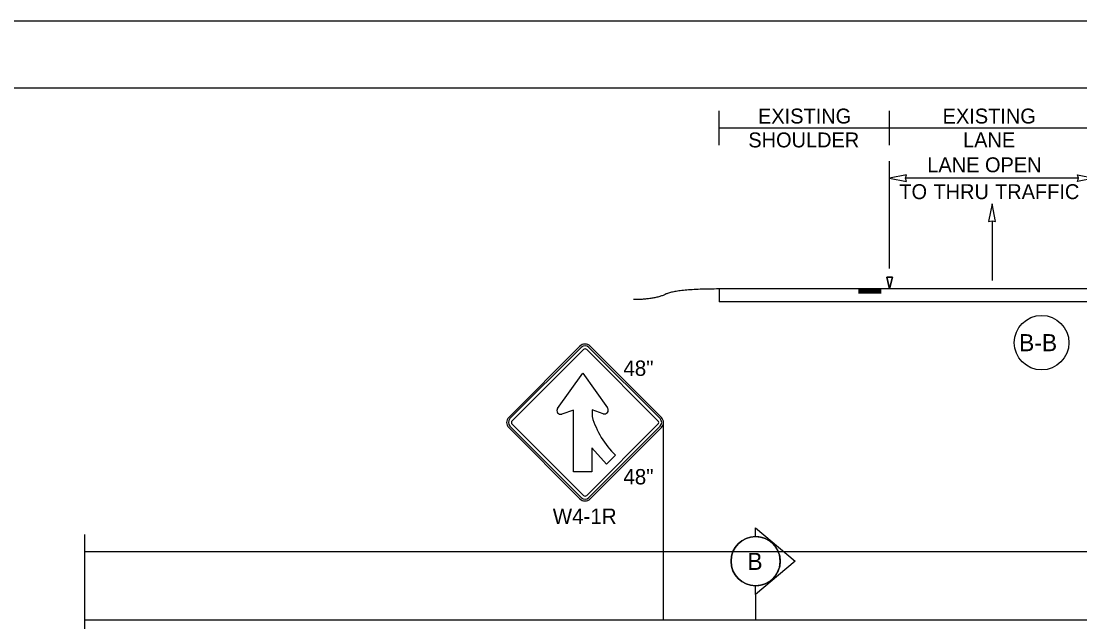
# Model space of a CAD drawing. Extents: x 99999 to 100116, y 99995 to 100013.
# Drawn here: x 100067.897 to 100072.862, y 100007.869 to 100010.687 of the extents above; entities that cross this region are included whole.
import ezdxf

# ---------------------------------------------------------------- set-up
doc = ezdxf.new("R2010")
doc.units = 0
for name, color, linetype in [('RD_MK_LineEdgeYellow', 7, 'Continuous'), ('SH_GI_PlotLimits', 7, 'Continuous'), ('SH_GI_SectionCut', 7, 'Continuous'), ('SH_GI_SheetBorder', 7, 'Continuous'), ('TR_SN_ConstructionSigns', 7, 'Continuous'), ('TR_WZ_ArrowLeftStrRightTurn', 7, 'Continuous'), ('TR_WZ_WorkZoneDetails', 7, 'Continuous')]:
    doc.layers.add(name, color=color, linetype=linetype)

msp = doc.modelspace()

# ---------------------------------------------------------------- linework, layer by layer
at = {"layer": 'RD_MK_LineEdgeYellow'}
msp.add_line((100068.195, 100007.8789), (100075.43, 100007.8789), dxfattribs=at)
at = {"layer": 'SH_GI_PlotLimits'}
msp.add_lwpolyline([(100059.0625, 99999.6875), (100076.0625, 99999.6875), (100076.0625, 100010.6875), (100059.0625, 100010.6875)], close=True, dxfattribs=at)
at = {"layer": 'SH_GI_SectionCut'}
for p, q in [((100071.3414, 100008.269), (100071.3414, 100008.3097)), ((100071.3414, 100008.3097), (100071.5275, 100008.1538)), ((100071.5275, 100008.1538), (100071.3414, 100007.9979)), ((100071.3414, 100007.9979), (100071.3414, 100008.0386)), ((100071.3414, 100007.9979), (100071.3414, 100007.8789))]:
    msp.add_line(p, q, dxfattribs=at)
msp.add_circle((100071.3414, 100008.1538), 0.1152, dxfattribs=at)
msp.add_circle((100071.3414, 100008.1538), 0.1152, dxfattribs=at)
for start, end in [(90.0016, 269.9972), (269.9972, 90.0016), (269.9972, 90.0016)]:
    msp.add_arc((100071.3414, 100008.1538), 0.1152, start, end, dxfattribs=at)
at = {"layer": 'SH_GI_SheetBorder'}
msp.add_line((100060, 100010.375), (100075.75, 100010.375), dxfattribs=at)
at = {"layer": 'TR_SN_ConstructionSigns'}
for p, q in [((100070.5176, 100009.1627), (100070.1835, 100008.8286)), ((100070.5236, 100009.1568), (100070.1895, 100008.8227)), ((100070.1994, 100008.8127), (100070.5336, 100009.1468)), ((100070.5495, 100009.1468), (100070.8836, 100008.8127)), ((100070.8935, 100008.8227), (100070.5594, 100009.1568)), ((100070.8995, 100008.8286), (100070.5654, 100009.1627)), ((100070.4127, 100008.871), (100070.5306, 100009.0367)), ((100070.5306, 100009.0367), (100070.6471, 100008.8728)), ((100070.4879, 100008.8629), (100070.433, 100008.8439)), ((100070.4879, 100008.5728), (100070.4879, 100008.8629)), ((100070.6266, 100008.8458), (100070.5747, 100008.8644)), ((100070.5747, 100008.8644), (100070.5747, 100008.832)), ((100070.5336, 100008.4627), (100070.1994, 100008.7968)), ((100070.8836, 100008.7968), (100070.5495, 100008.4627)), ((100070.1835, 100008.7809), (100070.5176, 100008.4468)), ((100070.1895, 100008.7869), (100070.5236, 100008.4528)), ((100070.5594, 100008.4528), (100070.8935, 100008.7869)), ((100070.5654, 100008.4468), (100070.8995, 100008.7809)), ((100070.6424, 100008.6097), (100070.5732, 100008.6862)), ((100070.5732, 100008.6862), (100070.5732, 100008.5728)), ((100070.6836, 100008.6509), (100070.6424, 100008.6097)), ((100070.5732, 100008.5728), (100070.4879, 100008.5728))]:
    msp.add_line(p, q, dxfattribs=at)
for centre, radius, start, end in [((100070.5415, 100009.1389), 0.0338, 45, 135), ((100070.5415, 100009.1389), 0.0253, 45, 135), ((100070.5415, 100009.1389), 0.0113, 45, 135), ((100070.4272, 100008.8607), 0.0177, 144.5862, 289.1062), ((100070.6326, 100008.8626), 0.0177, 250.3331, 35.4138), ((100070.2074, 100008.8048), 0.0338, 135, 225), ((100070.2074, 100008.8048), 0.0253, 135, 225), ((100070.2074, 100008.8048), 0.0113, 135, 225), ((100070.9878, 100008.9571), 0.4316, 196.843, 225.185), ((100070.8756, 100008.8048), 0.0113, 315, 45), ((100070.8756, 100008.8048), 0.0253, 315, 45), ((100070.8756, 100008.8048), 0.0338, 315, 45), ((100070.5415, 100008.4707), 0.0338, 225, 315), ((100070.5415, 100008.4707), 0.0253, 225, 315), ((100070.5415, 100008.4707), 0.0113, 225, 315)]:
    msp.add_arc(centre, radius, start, end, dxfattribs=at)
at = {"layer": 'TR_WZ_ArrowLeftStrRightTurn'}
msp.add_line((100072.45, 100009.7509), (100072.45, 100009.471), dxfattribs=at)
msp.add_lwpolyline([(100072.45, 100009.831), (100072.4335, 100009.747), (100072.45, 100009.7509), (100072.4664, 100009.747)], close=True, dxfattribs=at)
at = {"layer": 'TR_WZ_WorkZoneDetails'}
for p, q in [((100071.17, 100010.1063), (100071.17, 100010.2663)), ((100071.97, 100010.1063), (100071.97, 100010.2663)), ((100071.17, 100010.1863), (100071.97, 100010.1863)), ((100071.97, 100010.1863), (100072.93, 100010.1863)), ((100071.97, 100009.5269), (100071.97, 100010.0306)), ((100072.855, 100009.9506), (100072.045, 100009.9506)), ((100075.65, 100009.431), (100071.17, 100009.431)), ((100071.17, 100009.431), (100071.17, 100009.371)), ((100071.8236, 100009.4269), (100071.93, 100009.4269)), ((100071.8236, 100009.4224), (100071.93, 100009.4224)), ((100071.8236, 100009.4178), (100071.93, 100009.4178)), ((100071.8236, 100009.4137), (100071.93, 100009.4137)), ((100075.65, 100009.371), (100071.17, 100009.371)), ((100070.9094, 100007.8789), (100070.9094, 100008.8048)), ((100068.195, 100008.1989), (100075.43, 100008.1989))]:
    msp.add_line(p, q, dxfattribs=at)
for points in [[(100071.97, 100009.9506), (100072.0486, 100009.9352), (100072.045, 100009.9506), (100072.0486, 100009.966)], [(100072.93, 100009.9506), (100072.8514, 100009.9352), (100072.855, 100009.9506), (100072.8514, 100009.966)], [(100071.97, 100009.431), (100071.9566, 100009.4869), (100071.9833, 100009.4869)]]:
    msp.add_lwpolyline(points, close=True, dxfattribs=at)
for points in [[(100071.9833, 100009.4869), (100071.9566, 100009.4869), (100071.97, 100009.431), (100071.9833, 100009.4869)], [(100068.195, 100006.7109), (100068.195, 100007.433), (100068.131, 100007.433), (100068.259, 100007.5569), (100068.195, 100007.5569), (100068.195, 100008.2789)]]:
    msp.add_lwpolyline(points, dxfattribs=at)
msp.add_circle((100072.6826, 100009.1791), 0.128, dxfattribs=at)
msp.add_open_spline([(100071.17, 100009.431), (100070.9691, 100009.431), (100070.8687, 100009.3813), (100070.7683, 100009.3813)], degree=2, dxfattribs=at)

# ---------------------------------------------------------------- texts
at = {"layer": 'SH_GI_SectionCut'}
msp.add_text('B', height=0.08, rotation=0.0094, dxfattribs=at).set_placement((100071.3027, 100008.1131))
at = {"layer": 'TR_SN_ConstructionSigns'}
for s, p in [('48"', (100070.7213, 100009.0233)), ('48"', (100070.7213, 100008.5142)), ('W4-1R', (100070.3901, 100008.3289))]:
    msp.add_text(s, height=0.072, rotation=360, dxfattribs=at).set_placement(p)
at = {"layer": 'TR_WZ_WorkZoneDetails'}
for s, height, p in [('EXISTING', 0.07, (100071.3527, 100010.2073)), ('EXISTING', 0.07, (100072.2185, 100010.2073)), ('SHOULDER', 0.07, (100071.3073, 100010.0953)), ('LANE', 0.07, (100072.3142, 100010.0953)), ('LANE OPEN', 0.07, (100072.1466, 100009.9786)), ('TO', 0.07, (100072.0154, 100009.8526)), ('THRU', 0.07, (100072.1754, 100009.8526)), ('TRAFFIC', 0.07, (100072.4643, 100009.8526)), ('B-B', 0.08, (100072.577, 100009.1391))]:
    msp.add_text(s, height=height, dxfattribs=at).set_placement(p)

doc.saveas('drawing.dxf')
